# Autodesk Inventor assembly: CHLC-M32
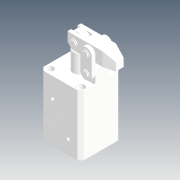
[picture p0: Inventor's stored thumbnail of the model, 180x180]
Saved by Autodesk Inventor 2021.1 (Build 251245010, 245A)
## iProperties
Company: Microsoft
Created: 2019-11
Part Number: CHLC-M32
Description: STEP AP214
Document SubType Name: Assembly
Designer: user
Title: CHLC-M32.STEP
Author: Windows
Revision Number: ÈÎºÎ
Sending System: SolidWorks 2015
Preprocessor: SwSTEP 2.0
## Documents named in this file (9)
- D:\Vault_2016\Projekty\Clamptek\Hydraulic\CHLC\CHLC-32\Inventor\CHLC-M32\CHLC-M32.iam
- D:\Vault_2016\Projekty\Clamptek\Hydraulic\CHLC\CHLC-32\Inventor\CHLC-M32\CHLC-M32-01.ipt
- D:\Vault_2016\Projekty\Clamptek\Hydraulic\CHLC\CHLC-32\Inventor\CHLC-M32\CHLC-32-08.ipt
- D:\Vault_2016\Projekty\Clamptek\Hydraulic\CHLC\CHLC-32\Inventor\CHLC-M32\CHLC-32-03.ipt
- D:\Vault_2016\Projekty\Clamptek\Hydraulic\CHLC\CHLC-32\Inventor\CHLC-M32\CHLC-32-02.ipt
- D:\Vault_2016\Projekty\Clamptek\Hydraulic\CHLC\CHLC-32\Inventor\CHLC-M32\CHLC-32-04.ipt
- D:\Vault_2016\Projekty\Clamptek\Hydraulic\CHLC\CHLC-32\Inventor\CHLC-M32\LHC01D-32-01.ipt
- D:\Vault_2016\Projekty\Clamptek\Hydraulic\CHLC\CHLC-32\Inventor\CHLC-M32\M6LS.ipt
- D:\Vault_2016\Projekty\Clamptek\Hydraulic\CHLC\CHLC-32\Inventor\CHLC-M32\Ñ¹±Û.ipt
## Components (16 placed, 16 different names)
1. CHLC-M32-01_1
2. CHLC-32-08_2
3. CHLC-32-03_3
4. CHLC-32-03_4
5. CHLC-32-02_5
6. CHLC-32-04_6
7. CHLC-32-04_7
8. LHC01D-32-01_8
9. LHC01D-32-01_9
10. LHC01D-32-01_10
11. LHC01D-32-01_11
12. LHC01D-32-01_12
13. LHC01D-32-01_13
14. M6LS_14
15. M6LS_15
16. Ñ¹±Û_16
